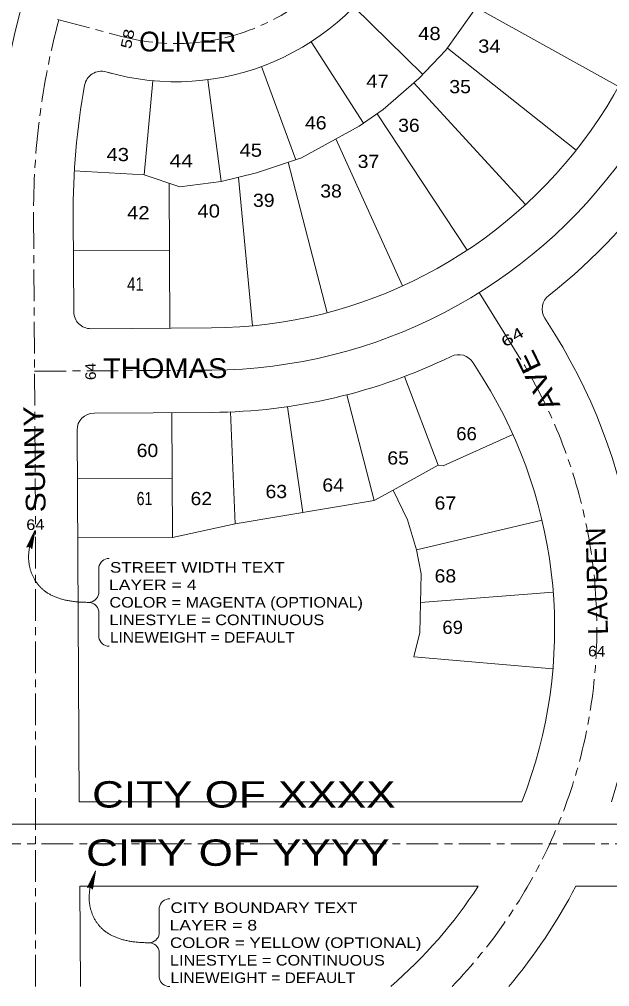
# Model space of a CAD drawing. Extents: x 6387474 to 6390971, y 1972046 to 1973920.
# Drawn here: x 6389192 to 6389640, y 1972046 to 1972779 of the extents above; entities that cross this region are included whole.
import ezdxf

# ---------------------------------------------------------------- set-up
doc = ezdxf.new("R2010")
doc.units = 0
doc.header["$LTSCALE"] = 4
doc.linetypes.add('LONG_DASH_SHORT_DASH', pattern=[9.9, 6, -1.2, 1.5, -1.2])
for name, color, linetype, lineweight in [('1', 7, 'Continuous', 13), ('2', 7, 'LONG_DASH_SHORT_DASH', 13), ('3', 7, 'Continuous', 13), ('4', 7, 'Continuous', 13), ('8', 7, 'Continuous', 13)]:
    doc.layers.add(name, color=color, linetype=linetype, lineweight=lineweight)
doc.layers.add('7', color=7, linetype='Continuous')

msp = doc.modelspace()

# ---------------------------------------------------------------- hatches: boundary and pattern name
at = {"layer": '8'}
for points in [[(6389197.52, 1972379.01), (6389198.028, 1972379.286), (6389203.731, 1972391.715)], [(6389198.028, 1972379.286), (6389198.586, 1972379.439), (6389203.731, 1972391.715)], [(6389198.586, 1972379.439), (6389199.164, 1972379.459), (6389203.731, 1972391.715)], [(6389199.164, 1972379.459), (6389199.731, 1972379.346), (6389203.731, 1972391.715)], [(6389199.731, 1972379.346), (6389200.257, 1972379.106), (6389203.731, 1972391.715)], [(6389203.731, 1972391.715), (6389200.257, 1972379.106), (6389200.713, 1972378.751)], [(6389203.731, 1972391.715), (6389200.713, 1972378.751), (6389201.076, 1972378.301)], [(6389203.731, 1972391.715), (6389201.076, 1972378.301), (6389201.327, 1972377.779)], [(6389243.489, 1972120.868), (6389243.997, 1972121.145), (6389249.699, 1972133.574)], [(6389243.997, 1972121.145), (6389244.554, 1972121.297), (6389249.699, 1972133.574)], [(6389244.554, 1972121.297), (6389245.132, 1972121.317), (6389249.699, 1972133.574)], [(6389245.132, 1972121.317), (6389245.699, 1972121.204), (6389249.699, 1972133.574)], [(6389245.699, 1972121.204), (6389246.225, 1972120.964), (6389249.699, 1972133.574)], [(6389249.699, 1972133.574), (6389246.225, 1972120.964), (6389246.682, 1972120.609)], [(6389249.699, 1972133.574), (6389246.682, 1972120.609), (6389247.045, 1972120.159)], [(6389249.699, 1972133.574), (6389247.045, 1972120.159), (6389247.295, 1972119.637)]]:
    msp.add_hatch(color=256, dxfattribs=at).paths.add_polyline_path(points)

# ---------------------------------------------------------------- linework, layer by layer
at = {"layer": '1'}
for p, q in [((6389461.201, 1972414.358), (6389475.567, 1972422.29)), ((6389475.567, 1972422.29), (6389486.58, 1972399.757)), ((6389355.672, 1972396.738), (6389461.201, 1972414.358)), ((6389308.137, 1972386.478), (6389355.672, 1972396.738)), ((6389486.58, 1972399.757), (6389493.356, 1972377.139)), ((6389236.138, 1972386.043), (6389308.137, 1972386.478)), ((6389493.265, 1972377.117), (6389496.876, 1972358.759)), ((6389496.876, 1972358.759), (6389495.978, 1972314.388)), ((6389495.978, 1972314.388), (6389491.183, 1972295.807)), ((6389491.183, 1972295.807), (6389596.897, 1972286.766))]:
    msp.add_line(p, q, dxfattribs=at)
at = {"layer": '2'}
for p, q in [((6389221.81, 1972779.1), (6389220.844, 1972779.357)), ((6389221.81, 1972779.1), (6389269.499, 1972766.403)), ((6389202.666, 1972629.265), (6389204.121, 1972388.749)), ((6389203.373, 1972512.497), (6389337.91, 1972513.311)), ((6389204.121, 1972045.989), (6389204.121, 1972388.749)), ((6389050.214, 1972153.984), (6389903.778, 1972153.984))]:
    msp.add_line(p, q, dxfattribs=at)
at = {"layer": '2', "linetype": 'Continuous'}
msp.add_line((6389540.906, 1972572.096), (6389571.1, 1972523.691), dxfattribs=at)
msp.add_arc((6389335.562, 1972901.304), 388, 270.34667, 18.92364, dxfattribs=at)
at = {"layer": '2'}
for centre, radius, start, end in [((6389310.662, 1972921.018), 160, 255.09194, 332.86738), ((6389771.656, 1972632.707), 569, 165.09129, 180.34667), ((6389240.198, 1972317.283), 390, 315.92273, 31.95472)]:
    msp.add_arc(centre, radius, start, end, dxfattribs=at)
at = {"layer": '3'}
for p, q in [((6389545.231, 1972797.842), (6389515.636, 1972755.89)), ((6389498.047, 1972737.54), (6389445.712, 1972788.797)), ((6389538.594, 1972788.433), (6389646.715, 1972728.329)), ((6389453.107, 1972700.641), (6389413.268, 1972762.295)), ((6389495.146, 1972734.517), (6389515.686, 1972755.913)), ((6389516.826, 1972757.577), (6389614.545, 1972680.16)), ((6389375.729, 1972743.572), (6389401.647, 1972672.9)), ((6389286.516, 1972661.434), (6389293.155, 1972732.83)), ((6389345.103, 1972656.261), (6389335.04, 1972733.597)), ((6389468.096, 1972710.928), (6389495.146, 1972734.517)), ((6389576.067, 1972638.828), (6389491.353, 1972731.233)), ((6389449.768, 1972698.349), (6389468.096, 1972710.928)), ((6389531.812, 1972604.282), (6389463.419, 1972707.738)), ((6389406.074, 1972674.393), (6389449.768, 1972698.349)), ((6389482.775, 1972577.168), (6389432.144, 1972688.693)), ((6389371.928, 1972662.882), (6389406.074, 1972674.393)), ((6389425.583, 1972556.873), (6389395.793, 1972670.927)), ((6389233.598, 1972664.568), (6389286.516, 1972661.434)), ((6389286.516, 1972661.434), (6389313.754, 1972652.361)), ((6389345.103, 1972656.261), (6389371.928, 1972662.881)), ((6389368.718, 1972546.857), (6389358.182, 1972659.489)), ((6389305.461, 1972655.124), (6389306.127, 1972545.119)), ((6389313.754, 1972652.361), (6389345.103, 1972656.261)), ((6389232.821, 1972603.677), (6389305.77, 1972604.118)), ((6389509.78, 1972441.178), (6389484.283, 1972508.516)), ((6389461.201, 1972414.358), (6389440.491, 1972494.622)), ((6389407.002, 1972405.308), (6389395.461, 1972485.597)), ((6389307.564, 1972481.127), (6389308.137, 1972386.478)), ((6389355.672, 1972396.738), (6389352.048, 1972481.627)), ((6389513.51, 1972440.632), (6389566.505, 1972464.551)), ((6389475.567, 1972422.29), (6389509.78, 1972441.178)), ((6389509.78, 1972441.178), (6389513.51, 1972440.632)), ((6389235.866, 1972431.042), (6389307.865, 1972431.478)), ((6389493.265, 1972377.117), (6389588.592, 1972399.657)), ((6389496.44, 1972337.184), (6389597.123, 1972345.005))]:
    msp.add_line(p, q, dxfattribs=at)
at = {"layer": '4'}
for p, q in [((6389257.524, 1972739.581), (6389262.038, 1972738.379)), ((6389232.665, 1972629.446), (6389233.1, 1972557.677)), ((6389590.633, 1972552.839), (6389598.251, 1972540.626)), ((6389246.178, 1972544.756), (6389337.716, 1972545.31)), ((6389536.33, 1972518.968), (6389543.949, 1972506.755)), ((6389248.565, 1972480.77), (6389338.104, 1972481.311)), ((6389235.644, 1972467.691), (6389237.349, 1972185.984)), ((6389237.349, 1972185.984), (6389573.251, 1972185.984)), ((6389237.736, 1972121.983), (6389540.234, 1972121.983)), ((6389237.736, 1972121.983), (6389238.196, 1972045.989)), ((6389614.286, 1972121.983), (6389908.78, 1972121.983))]:
    msp.add_line(p, q, dxfattribs=at)
for centre, radius, start, end in [((6389771.661, 1972632.72), 599, 137.65605, 180.34667), ((6389335.562, 1972901.304), 420, 307.91924, 18.92365), ((6389335.562, 1972901.304), 356, 270.34667, 18.92365), ((6389310.662, 1972921.018), 189, 253.67626, 332.86738), ((6389254.18, 1972727.019), 13, 75.09194, 169.67106), ((6389771.656, 1972632.707), 539, 169.67106, 180.34667), ((6389601.663, 1972559.72), 13, 127.91924, 211.95472), ((6389246.099, 1972557.756), 13, 180.34667, 270.34667), ((6389240.198, 1972317.283), 422, 341.87222, 31.95472), ((6389335.562, 1972901.304), 420, 270.34667, 295.98864), ((6389525.3, 1972512.088), 13, 31.95472, 115.98864), ((6389240.198, 1972317.283), 358, 338.48409, 31.95472), ((6389248.644, 1972467.77), 13, 90.34667, 180.34667), ((6389240.198, 1972317.283), 358, 310.72876, 326.939), ((6389240.198, 1972317.283), 422, 319.99318, 332.43226)]:
    msp.add_arc(centre, radius, start, end, dxfattribs=at)
at = {"layer": '8'}
for p, q in [((6389252.13, 1972363.859), (6389252.13, 1972343.879)), ((6389252.13, 1972310.573), (6389252.13, 1972330.553)), ((6389050.214, 1972169.009), (6389919.45, 1972169.009)), ((6389298.098, 1972105.718), (6389298.098, 1972085.738)), ((6389298.098, 1972052.432), (6389298.098, 1972072.412))]:
    msp.add_line(p, q, dxfattribs=at)
for points in [[(6389197.52, 1972379.01), (6389198.028, 1972379.286), (6389203.731, 1972391.715)], [(6389198.028, 1972379.286), (6389198.586, 1972379.439), (6389203.731, 1972391.715)], [(6389198.586, 1972379.439), (6389199.164, 1972379.459), (6389203.731, 1972391.715)], [(6389199.164, 1972379.459), (6389199.731, 1972379.346), (6389203.731, 1972391.715)], [(6389199.731, 1972379.346), (6389200.257, 1972379.106), (6389203.731, 1972391.715)], [(6389203.731, 1972391.715), (6389200.257, 1972379.106), (6389200.713, 1972378.751)], [(6389203.731, 1972391.715), (6389200.713, 1972378.751), (6389201.076, 1972378.301)], [(6389203.731, 1972391.715), (6389201.076, 1972378.301), (6389201.327, 1972377.779)], [(6389243.489, 1972120.868), (6389243.997, 1972121.145), (6389249.699, 1972133.574)], [(6389243.997, 1972121.145), (6389244.554, 1972121.297), (6389249.699, 1972133.574)], [(6389244.554, 1972121.297), (6389245.132, 1972121.317), (6389249.699, 1972133.574)], [(6389245.132, 1972121.317), (6389245.699, 1972121.204), (6389249.699, 1972133.574)], [(6389245.699, 1972121.204), (6389246.225, 1972120.964), (6389249.699, 1972133.574)], [(6389249.699, 1972133.574), (6389246.225, 1972120.964), (6389246.682, 1972120.609)], [(6389249.699, 1972133.574), (6389246.682, 1972120.609), (6389247.045, 1972120.159)], [(6389249.699, 1972133.574), (6389247.045, 1972120.159), (6389247.295, 1972119.637)]]:
    msp.add_lwpolyline(points, close=True, dxfattribs=at)
for points in [[(6389201.327, 1972377.779), (6389203.731, 1972391.715), (6389197.521, 1972379.01)], [(6389198.974, 1972373.962), (6389199.02, 1972374.581), (6389199.076, 1972375.203), (6389199.142, 1972375.828), (6389199.219, 1972376.456), (6389199.305, 1972377.087), (6389199.401, 1972377.721), (6389199.507, 1972378.358), (6389199.624, 1972378.997), (6389199.75, 1972379.64), (6389199.886, 1972380.286), (6389200.032, 1972380.934), (6389200.188, 1972381.586), (6389200.355, 1972382.241), (6389200.531, 1972382.898), (6389200.717, 1972383.559), (6389200.913, 1972384.222), (6389201.119, 1972384.888), (6389201.335, 1972385.558), (6389201.562, 1972386.23), (6389201.798, 1972386.905), (6389202.044, 1972387.584), (6389202.3, 1972388.265), (6389202.566, 1972388.949), (6389202.842, 1972389.636), (6389203.128, 1972390.326), (6389203.425, 1972391.019), (6389203.731, 1972391.715)], [(6389209.838, 1972346.849), (6389209.379, 1972347.246), (6389208.929, 1972347.651), (6389208.489, 1972348.065), (6389208.058, 1972348.486), (6389207.638, 1972348.915), (6389207.227, 1972349.352), (6389206.826, 1972349.798), (6389206.434, 1972350.251), (6389206.052, 1972350.712), (6389205.68, 1972351.182), (6389205.318, 1972351.659), (6389204.965, 1972352.145), (6389204.622, 1972352.638), (6389204.289, 1972353.14), (6389203.965, 1972353.648), (6389203.652, 1972354.161), (6389203.348, 1972354.676), (6389203.055, 1972355.195), (6389202.771, 1972355.716), (6389202.497, 1972356.24), (6389202.234, 1972356.768), (6389201.98, 1972357.298), (6389201.737, 1972357.831), (6389201.503, 1972358.367), (6389201.279, 1972358.906), (6389201.066, 1972359.448), (6389200.862, 1972359.993), (6389200.669, 1972360.541), (6389200.485, 1972361.092), (6389200.311, 1972361.646), (6389200.148, 1972362.203), (6389199.994, 1972362.763), (6389199.85, 1972363.326), (6389199.717, 1972363.892), (6389199.593, 1972364.46), (6389199.479, 1972365.032), (6389199.376, 1972365.607), (6389199.282, 1972366.184), (6389199.198, 1972366.765), (6389199.125, 1972367.348), (6389199.061, 1972367.935), (6389199.007, 1972368.524), (6389198.964, 1972369.117), (6389198.93, 1972369.712), (6389198.906, 1972370.31), (6389198.892, 1972370.911), (6389198.889, 1972371.516), (6389198.895, 1972372.123), (6389198.911, 1972372.733), (6389198.938, 1972373.346), (6389198.974, 1972373.962)], [(6389244.244, 1972337.216), (6389243.309, 1972337.22), (6389242.383, 1972337.232), (6389241.467, 1972337.252), (6389240.561, 1972337.281), (6389239.665, 1972337.317), (6389238.778, 1972337.361), (6389237.902, 1972337.413), (6389237.034, 1972337.473), (6389236.177, 1972337.541), (6389235.329, 1972337.618), (6389234.491, 1972337.702), (6389233.663, 1972337.794), (6389232.844, 1972337.894), (6389232.035, 1972338.003), (6389231.236, 1972338.119), (6389230.446, 1972338.243), (6389229.667, 1972338.376), (6389228.896, 1972338.516), (6389228.136, 1972338.665), (6389227.385, 1972338.821), (6389226.644, 1972338.986), (6389225.913, 1972339.158), (6389225.191, 1972339.339), (6389224.48, 1972339.527), (6389223.777, 1972339.724), (6389223.085, 1972339.928), (6389222.402, 1972340.141), (6389221.729, 1972340.362), (6389221.066, 1972340.59), (6389220.412, 1972340.827), (6389219.768, 1972341.072), (6389219.134, 1972341.325), (6389218.51, 1972341.585), (6389217.895, 1972341.854), (6389217.29, 1972342.131), (6389216.694, 1972342.416), (6389216.109, 1972342.709), (6389215.533, 1972343.01), (6389214.967, 1972343.318), (6389214.41, 1972343.635), (6389213.863, 1972343.96), (6389213.326, 1972344.293), (6389212.799, 1972344.634), (6389212.281, 1972344.983), (6389211.773, 1972345.34), (6389211.275, 1972345.706), (6389210.786, 1972346.079), (6389210.307, 1972346.46), (6389209.838, 1972346.849)], [(6389247.295, 1972119.637), (6389249.699, 1972133.574), (6389243.489, 1972120.868)], [(6389244.942, 1972115.82), (6389244.989, 1972116.439), (6389245.045, 1972117.061), (6389245.111, 1972117.686), (6389245.187, 1972118.314), (6389245.274, 1972118.945), (6389245.37, 1972119.579), (6389245.476, 1972120.216), (6389245.592, 1972120.856), (6389245.718, 1972121.498), (6389245.855, 1972122.144), (6389246.001, 1972122.793), (6389246.157, 1972123.444), (6389246.323, 1972124.099), (6389246.499, 1972124.756), (6389246.686, 1972125.417), (6389246.882, 1972126.08), (6389247.088, 1972126.747), (6389247.304, 1972127.416), (6389247.53, 1972128.088), (6389247.766, 1972128.764), (6389248.012, 1972129.442), (6389248.269, 1972130.123), (6389248.535, 1972130.807), (6389248.811, 1972131.494), (6389249.097, 1972132.184), (6389249.393, 1972132.877), (6389249.699, 1972133.573)], [(6389255.807, 1972088.707), (6389255.347, 1972089.104), (6389254.897, 1972089.509), (6389254.457, 1972089.923), (6389254.027, 1972090.344), (6389253.606, 1972090.773), (6389253.195, 1972091.211), (6389252.794, 1972091.656), (6389252.403, 1972092.109), (6389252.021, 1972092.571), (6389251.649, 1972093.04), (6389251.286, 1972093.517), (6389250.934, 1972094.003), (6389250.591, 1972094.496), (6389250.257, 1972094.998), (6389249.934, 1972095.507), (6389249.62, 1972096.019), (6389249.317, 1972096.535), (6389249.023, 1972097.053), (6389248.74, 1972097.574), (6389248.466, 1972098.099), (6389248.202, 1972098.626), (6389247.949, 1972099.156), (6389247.705, 1972099.689), (6389247.472, 1972100.225), (6389247.248, 1972100.765), (6389247.034, 1972101.307), (6389246.831, 1972101.852), (6389246.637, 1972102.4), (6389246.453, 1972102.951), (6389246.28, 1972103.505), (6389246.116, 1972104.061), (6389245.963, 1972104.621), (6389245.819, 1972105.184), (6389245.685, 1972105.75), (6389245.562, 1972106.318), (6389245.448, 1972106.89), (6389245.344, 1972107.465), (6389245.251, 1972108.042), (6389245.167, 1972108.623), (6389245.093, 1972109.206), (6389245.03, 1972109.793), (6389244.976, 1972110.382), (6389244.932, 1972110.975), (6389244.898, 1972111.57), (6389244.875, 1972112.168), (6389244.861, 1972112.77), (6389244.857, 1972113.374), (6389244.864, 1972113.981), (6389244.88, 1972114.591), (6389244.906, 1972115.204), (6389244.942, 1972115.82)], [(6389290.212, 1972079.075), (6389289.277, 1972079.079), (6389288.352, 1972079.091), (6389287.436, 1972079.111), (6389286.53, 1972079.139), (6389285.634, 1972079.175), (6389284.747, 1972079.219), (6389283.87, 1972079.271), (6389283.003, 1972079.331), (6389282.145, 1972079.4), (6389281.298, 1972079.476), (6389280.46, 1972079.56), (6389279.631, 1972079.652), (6389278.813, 1972079.753), (6389278.004, 1972079.861), (6389277.204, 1972079.977), (6389276.415, 1972080.102), (6389275.635, 1972080.234), (6389274.865, 1972080.374), (6389274.105, 1972080.523), (6389273.354, 1972080.679), (6389272.613, 1972080.844), (6389271.882, 1972081.016), (6389271.16, 1972081.197), (6389270.448, 1972081.385), (6389269.746, 1972081.582), (6389269.054, 1972081.787), (6389268.371, 1972081.999), (6389267.698, 1972082.22), (6389267.034, 1972082.449), (6389266.381, 1972082.685), (6389265.737, 1972082.93), (6389265.103, 1972083.183), (6389264.478, 1972083.443), (6389263.863, 1972083.712), (6389263.258, 1972083.989), (6389262.663, 1972084.274), (6389262.077, 1972084.567), (6389261.501, 1972084.868), (6389260.935, 1972085.177), (6389260.379, 1972085.494), (6389259.832, 1972085.819), (6389259.295, 1972086.152), (6389258.767, 1972086.493), (6389258.249, 1972086.842), (6389257.741, 1972087.199), (6389257.243, 1972087.564), (6389256.755, 1972087.937), (6389256.276, 1972088.318), (6389255.807, 1972088.707)]]:
    msp.add_lwpolyline(points, dxfattribs=at)
for centre, radius, start, end in [((6389198.962, 1972376.967), 2.5, 18.95091, 125.21111), ((6389260.019, 1972362.522), 8, 90, 170.38048), ((6389244.244, 1972345.216), 8, 270, 350.38048), ((6389244.244, 1972329.216), 8, 9.61952, 90), ((6389260.019, 1972311.91), 8, 189.61952, 270), ((6389244.93, 1972118.826), 2.5, 18.95091, 125.21111), ((6389305.988, 1972104.381), 8, 90, 170.38048), ((6389290.213, 1972087.074), 8, 270, 350.38048), ((6389290.213, 1972071.074), 8, 9.61952, 90), ((6389305.987, 1972053.768), 8, 189.61952, 270)]:
    msp.add_arc(centre, radius, start, end, dxfattribs=at)

# ---------------------------------------------------------------- texts
at = {"layer": '2'}
for s, rotation, p in [('OLIVER', 359.712, (6389282.793, 1972755.055)), ('LAUREN', 91.449, (6389638.699, 1972312.817))]:
    msp.add_text(s, height=15, rotation=rotation, dxfattribs=at).set_placement(p)
for s, rotation, width, p in [('AVE', 116.204, 1.2, (6389602.771, 1972486.633)), ('THOMAS ', 0.064, 1.1, (6389255.374, 1972507.21)), ('SUNNY ', 91.449, 1.15, (6389211.934, 1972405.522))]:
    msp.add_text(s, height=15, rotation=rotation, dxfattribs=dict(at, width=width)).set_placement(p)
at = {"layer": '4'}
for s, rotation, width, p in [('58', 78.594, 1.25, (6389276.492, 1972756.516)), ('64', 31.522, 1.5, (6389560.606, 1972530.368)), ('64', 90.902, 1.1, (6389250.023, 1972505.834)), ('64', 1.579, 1.15, (6389197.237, 1972392.027)), ('64', 358.932, 1.1, (6389623.518, 1972296.273))]:
    msp.add_text(s, height=8, rotation=rotation, dxfattribs=dict(at, width=width)).set_placement(p)
at = {"layer": '7'}
for s, width, p in [('48', 1.15, (6389494.556, 1972763.621)), ('34', 1.15, (6389540.082, 1972754.054)), ('47', 1.15, (6389455.18, 1972727.432)), ('35', 1.1, (6389518.257, 1972723.345)), ('46', 1.1, (6389408.687, 1972695.872)), ('36', 1.1, (6389479.396, 1972694.007)), ('43', 1.15, (6389257.996, 1972671.827)), ('45', 1.15, (6389358.97, 1972675.149)), ('44', 1.2, (6389305.876, 1972667.082)), ('37', 1.1, (6389448.688, 1972666.647)), ('38', 1.1, (6389420.28, 1972644.231)), ('39', 1.1, (6389369.238, 1972637.14)), ('42', 1.15, (6389273.641, 1972627.698)), ('40', 1.15, (6389327.046, 1972629.074)), ('41', 0.85, (6389273.641, 1972573.604)), ('66', 1.05, (6389523.496, 1972460.147)), ('60', 1.1, (6389280.911, 1972447.427)), ('65', 1.1, (6389471.195, 1972441.732)), ('65', 1.1, (6389471.195, 1972441.732)), ('64', 1.1, (6389421.875, 1972421.172)), ('63', 1.1, (6389378.741, 1972416.278)), ('61', 0.8, (6389280.911, 1972410.938)), ('61', 0.8, (6389280.911, 1972410.938)), ('62', 1.1, (6389321.821, 1972410.938)), ('67', 1.1, (6389507.066, 1972407.531)), ('68', 1.1, (6389507.066, 1972352.285)), ('69', 1.05, (6389512.981, 1972313.263))]:
    msp.add_text(s, height=10, dxfattribs=dict(at, width=width)).set_placement(p)
at = {"layer": '8'}
for s, height, width, p in [('STREET WIDTH TEXT', 8, 1.2, (6389260.664, 1972359.756)), ('LAYER = 4', 8, 1.25, (6389259.852, 1972346.508)), ('COLOR = MAGENTA (OPTIONAL)', 8, 1.15, (6389260.244, 1972333.25)), ('LINESTYLE = CONTINUOUS', 8, 1.15, (6389260.244, 1972319.93)), ('LINEWEIGHT = DEFAULT', 8, 1.1, (6389260.636, 1972306.672)), ('CITY OF XXXX', 20, 1.25, (6389247.066, 1972181.587)), ('CITY OF YYYY', 20, 1.25, (6389242.503, 1972137.41)), ('CITY BOUNDARY TEXT', 8, 1.2, (6389306.632, 1972101.614)), ('LAYER = 8', 8, 1.25, (6389305.82, 1972088.366)), ('COLOR = YELLOW (OPTIONAL)', 8, 1.2, (6389306.212, 1972075.108)), ('LINESTYLE = CONTINUOUS', 8, 1.15, (6389306.212, 1972061.788)), ('LINEWEIGHT = DEFAULT', 8, 1.1, (6389306.604, 1972048.53))]:
    msp.add_text(s, height=height, dxfattribs=dict(at, width=width)).set_placement(p)

doc.saveas('drawing.dxf')
